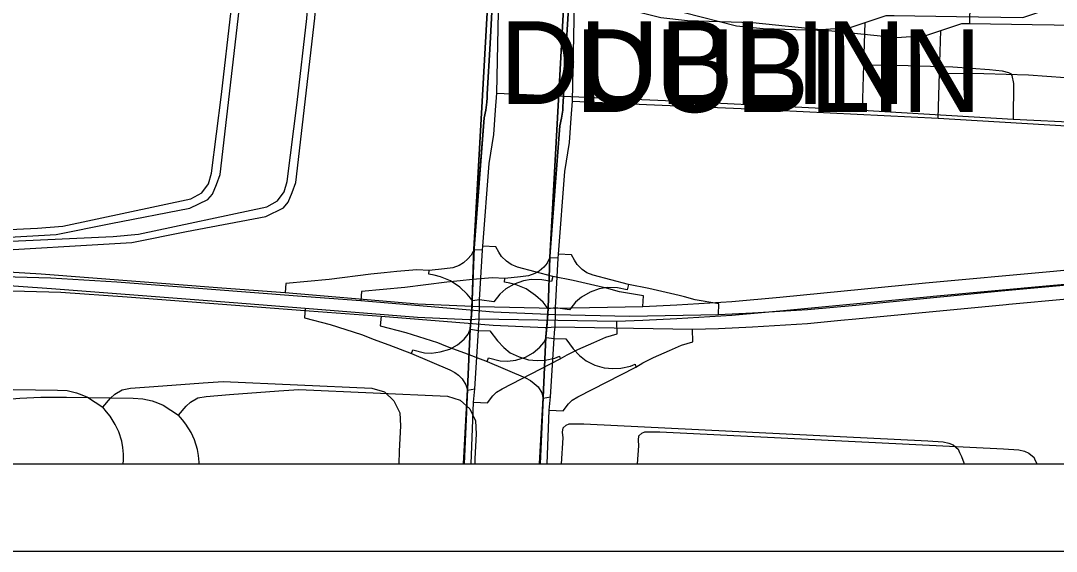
# Model space of a CAD drawing. Extents: x -38.2 to 41.9, y -4 to 24.9.
# Drawn here: x 5.806 to 6.989, y 14 to 14.606 of the extents above; entities that cross this region are included whole.
import ezdxf

# ---------------------------------------------------------------- set-up
doc = ezdxf.new("R2010")
doc.units = 0
for name, color, linetype in [('Default', 7, 'Continuous'), ('GM_X_City_Street', 7, 'Continuous'), ('GM_X_Corporation_Text', 7, 'Continuous'), ('GM_X_County_Road', 7, 'Continuous'), ('GM_X_Interchange_Ramps', 7, 'Continuous'), ('GM_X_Interstate_Location', 7, 'Continuous'), ('GM_X_Interstate_Route', 7, 'Continuous'), ('GM_X_Interstate_Shield', 7, 'Continuous'), ('MT_X_Cells', 7, 'Continuous'), ('SC_Scratch1', 7, 'Continuous'), ('SH_Cut_Line', 7, 'Continuous'), ('SH_Data', 7, 'Continuous')]:
    doc.layers.add(name, color=color, linetype=linetype)

msp = doc.modelspace()

# ---------------------------------------------------------------- linework, layer by layer
at = {"layer": 'Default'}
msp.add_lwpolyline([(2.1, 14.1), (6.3118, 14.1), (6.3164, 14.1849), (6.3196, 14.2542), (6.3213, 14.2711), (6.322, 14.2869), (6.3239, 14.3451), (6.3356, 14.4954), (6.3376, 14.5042), (6.3388, 14.5132), (6.3391, 14.5181), (6.3392, 14.5223), (6.3425, 14.5802), (6.3449, 14.6238), (6.3433, 14.6465), (6.3458, 14.7059), (6.3476, 14.7572), (6.3486, 14.779), (6.3534, 14.8901), (6.365, 15.1468), (6.3733, 15.33), (6.3957, 15.7611)], dxfattribs=at)
at = {"layer": 'GM_X_City_Street'}
msp.add_line((6.3206, 14.1), (6.3235, 14.1704), dxfattribs=at)
for points in [[(6.35, 14.5236), (6.3523, 14.6354), (6.3635, 14.8901)], [(5.2964, 14.3406), (5.4946, 14.3569), (5.6505, 14.3609), (5.8256, 14.3691), (5.8543, 14.3717), (6.0007, 14.4027), (6.0132, 14.4096), (6.0207, 14.42), (6.0241, 14.432), (6.0357, 14.5222), (6.0468, 14.618), (6.0558, 14.7287)], [(5.2978, 14.3315), (5.5096, 14.3476), (5.6655, 14.3516), (5.8468, 14.3621), (5.909, 14.3746), (5.9996, 14.392), (6.0199, 14.4019), (6.0253, 14.4081), (6.0299, 14.4192), (6.034, 14.4306), (6.0558, 14.6186), (6.0639, 14.7286)], [(6.3523, 14.6354), (6.418, 14.6322), (6.4498, 14.6297), (6.4776, 14.6249), (6.5372, 14.6099), (6.5678, 14.6067), (6.6425, 14.6042), (6.72, 14.5965), (6.7537, 14.5988), (6.7708, 14.6045), (6.7946, 14.6123), (6.8037, 14.6122), (6.8751, 14.6112), (6.9508, 14.6101), (6.9749, 14.618), (6.9983, 14.6201)], [(6.7677, 14.5042), (6.7693, 14.5558), (6.7708, 14.6045)], [(6.7693, 14.5558), (6.8197, 14.5552), (6.8709, 14.5536), (6.9128, 14.5507), (6.9273, 14.5489), (6.9345, 14.5471), (6.9366, 14.5462), (6.9382, 14.5439), (6.9401, 14.5345), (6.9397, 14.4938)], [(6.3341, 14.3489), (6.3413, 14.4432), (6.3465, 14.4764), (6.3485, 14.5042), (6.35, 14.5236)], [(6.35, 14.5236), (6.4345, 14.5198), (6.5518, 14.5147), (6.7677, 14.5042), (6.9397, 14.4938), (7.0973, 14.4863), (7.2194, 14.4805)], [(6.3296, 14.2594), (6.33, 14.2657), (6.3304, 14.2797), (6.3304, 14.2875), (6.3335, 14.3442), (6.3341, 14.3489)], [(6.3235, 14.1704), (6.325, 14.1857), (6.3292, 14.2525), (6.3296, 14.2594)], [(5.3301, 14.2038), (5.3623, 14.2023), (5.3911, 14.2005), (5.4282, 14.1983), (5.5962, 14.1881), (5.6279, 14.1859), (5.6713, 14.1832), (5.6952, 14.1824), (5.7186, 14.184), (5.7427, 14.1853), (5.772, 14.1852), (5.8481, 14.1841), (5.8593, 14.1836), (5.87, 14.1811), (5.8761, 14.179), (5.8824, 14.1763), (5.9, 14.1647)], [(5.9, 14.1647), (5.9087, 14.175), (5.9138, 14.1797), (5.9222, 14.1844), (5.9316, 14.1863), (5.9584, 14.1884), (6.0145, 14.1926), (6.0373, 14.194), (6.2073, 14.1866), (6.2216, 14.1821), (6.2326, 14.1719), (6.2392, 14.1583), (6.2401, 14.1433), (6.2386, 14.1146), (6.2381, 14.1)], [(5.9233, 14.1), (5.9235, 14.104), (5.9235, 14.111), (5.9229, 14.1185), (5.9218, 14.1257), (5.9183, 14.1367), (5.9143, 14.1449), (5.9083, 14.1546), (5.9044, 14.1593), (5.9, 14.1647)], [(6.4239, 14.1), (6.4257, 14.1296), (6.4252, 14.1363), (6.4259, 14.1412), (6.4292, 14.1442)], [(6.4292, 14.1442), (6.4326, 14.1458), (6.4496, 14.1456), (6.8424, 14.1263), (6.8597, 14.1252), (6.8664, 14.1237), (6.8711, 14.1215), (6.8772, 14.1163)], [(6.8839, 14.1), (6.8838, 14.1009), (6.8813, 14.1081), (6.8788, 14.1125), (6.8772, 14.1163)]]:
    msp.add_lwpolyline(points, dxfattribs=at)
at = {"layer": 'GM_X_County_Road'}
for points in [[(6.3957, 15.7611), (6.3733, 15.33), (6.365, 15.1468), (6.3534, 14.8903), (6.3486, 14.779), (6.3476, 14.7572), (6.3458, 14.7059), (6.3433, 14.6465), (6.3449, 14.6238), (6.3425, 14.5802), (6.3392, 14.5223), (6.3391, 14.5181), (6.3388, 14.5132), (6.3376, 14.5042), (6.3356, 14.4954), (6.3241, 14.3464), (6.322, 14.2871), (6.3213, 14.2711), (6.3196, 14.2542), (6.3164, 14.1849), (6.3118, 14.1), (8.9, 14.1)], [(2.1, 14.1), (6.3987, 14.1), (6.4028, 14.1757), (6.4061, 14.245), (6.4077, 14.2619), (6.4085, 14.2777), (6.4104, 14.3359), (6.4221, 14.4862), (6.4241, 14.495), (6.4253, 14.504), (6.4255, 14.5089), (6.4257, 14.5131), (6.4289, 14.5711), (6.4314, 14.6146), (6.4298, 14.6373), (6.4323, 14.6967), (6.4341, 14.748), (6.4351, 14.7698), (6.4399, 14.8809), (6.4515, 15.1376), (6.4598, 15.3208), (6.4822, 15.7519)], [(6.4822, 15.7519), (6.4598, 15.3208), (6.4515, 15.1376), (6.4399, 14.8811), (6.4351, 14.7698), (6.4341, 14.748), (6.4323, 14.6967), (6.4298, 14.6373), (6.4314, 14.6146), (6.4289, 14.5711), (6.4257, 14.5131), (6.4255, 14.5089), (6.4253, 14.504), (6.4241, 14.495), (6.4221, 14.4862), (6.4105, 14.3372), (6.4085, 14.2779), (6.4077, 14.2619), (6.4061, 14.245), (6.4028, 14.1757), (6.3987, 14.1), (8.9, 14.1)]]:
    msp.add_lwpolyline(points, dxfattribs=at)
at = {"layer": 'GM_X_Interchange_Ramps'}
for points in [[(2.1, 14.1), (6.3126, 14.1), (6.3164, 14.1849), (6.3196, 14.2542), (6.3207, 14.2654), (6.322, 14.2806), (6.322, 14.2869), (6.3239, 14.3451), (6.3402, 14.6363), (6.3534, 14.8912), (6.3648, 15.1855), (6.3744, 15.3416), (6.3746, 15.3485), (6.3792, 15.4548), (6.3824, 15.5439), (6.3986, 15.8377), (6.4038, 15.9323), (6.4072, 16.1101), (6.413, 16.3602), (5.9853, 16.3764), (5.6874, 16.3954)], [(2.1, 14.1), (6.3995, 14.1), (6.4028, 14.1757), (6.4061, 14.245), (6.4072, 14.2562), (6.4084, 14.2714), (6.4085, 14.2777), (6.4104, 14.3359), (6.4267, 14.6271), (6.4399, 14.882), (6.4513, 15.1763), (6.4608, 15.3324), (6.4611, 15.3393), (6.4657, 15.4456), (6.4689, 15.5348), (6.4851, 15.8285), (6.4903, 15.9231), (6.4937, 16.1009), (6.4995, 16.351), (6.0718, 16.3672), (5.7739, 16.3862)], [(7.1336, 16.3198), (6.4263, 16.3595), (6.413, 16.3602), (6.4072, 16.1101), (6.4038, 15.9323), (6.3986, 15.8377), (6.3824, 15.5439), (6.3792, 15.4548), (6.3746, 15.3485), (6.3744, 15.3416), (6.3648, 15.1855), (6.3534, 14.8912), (6.3402, 14.6363), (6.3239, 14.3451), (6.322, 14.2869), (6.322, 14.2806), (6.3207, 14.2654), (6.3196, 14.2542), (6.3164, 14.1849), (6.3126, 14.1), (8.8984, 14.1)], [(7.2201, 16.3106), (6.5128, 16.3503), (6.4995, 16.351), (6.4937, 16.1009), (6.4903, 15.9231), (6.4851, 15.8285), (6.4689, 15.5348), (6.4657, 15.4456), (6.4611, 15.3393), (6.4608, 15.3324), (6.4513, 15.1763), (6.4399, 14.882), (6.4267, 14.6271), (6.4104, 14.3359), (6.4085, 14.2777), (6.4084, 14.2714), (6.4072, 14.2562), (6.4061, 14.245), (6.4028, 14.1757), (6.3995, 14.1), (8.9, 14.1)], [(6.4142, 14.3142), (6.3738, 14.3246), (6.3665, 14.3276), (6.3611, 14.3314), (6.3554, 14.337), (6.3522, 14.3419), (6.349, 14.3481), (6.3341, 14.3489)], [(6.3231, 14.3425), (6.3209, 14.3384), (6.3171, 14.3341), (6.312, 14.3295), (6.3071, 14.3268), (6.2999, 14.3241), (6.2904, 14.3227), (6.2726, 14.3209)], [(6.3335, 14.3442), (6.3241, 14.3446), (6.3231, 14.3425)], [(6.2215, 14.3183), (6.2063, 14.3166), (6.1585, 14.3106), (6.1089, 14.306), (6.1083, 14.2957)], [(6.2726, 14.3209), (6.2585, 14.3218), (6.2357, 14.3198), (6.2215, 14.3183)], [(6.32, 14.2891), (6.3163, 14.2939), (6.3077, 14.3017), (6.2972, 14.309), (6.2856, 14.3138), (6.2785, 14.3156), (6.2724, 14.3166), (6.2726, 14.3209)], [(6.4142, 14.3142), (6.4126, 14.3082), (6.4013, 14.3103), (6.3894, 14.3106), (6.3805, 14.309), (6.37, 14.3052), (6.3603, 14.2998), (6.3535, 14.2939), (6.3467, 14.285), (6.3304, 14.2875)], [(6.4778, 14.2998), (6.4717, 14.3014), (6.4372, 14.3095), (6.4142, 14.3142)], [(6.3304, 14.2875), (6.3223, 14.2863), (6.32, 14.2891)], [(6.5167, 14.2799), (6.5174, 14.2921), (6.4901, 14.2967), (6.4778, 14.2998)], [(6.1313, 14.2778), (6.1304, 14.267), (6.1598, 14.2593), (6.1956, 14.2477), (6.2004, 14.2458)], [(6.319, 14.2518), (6.3198, 14.2537), (6.3292, 14.2525)], [(6.4225, 14.2198), (6.4303, 14.2244), (6.4426, 14.2306), (6.4609, 14.2388), (6.4744, 14.2448), (6.4875, 14.2486), (6.487, 14.2631)], [(6.2004, 14.2458), (6.209, 14.2424), (6.2267, 14.2358), (6.2525, 14.2261)], [(6.2525, 14.2261), (6.2541, 14.2304), (6.2675, 14.2267), (6.2756, 14.2264), (6.2853, 14.2278), (6.2964, 14.231), (6.305, 14.2359), (6.3128, 14.2426), (6.3174, 14.248), (6.319, 14.2518)], [(6.3292, 14.2525), (6.3422, 14.2521), (6.3508, 14.2404), (6.3579, 14.2329), (6.3654, 14.227), (6.3754, 14.2221), (6.3862, 14.2189), (6.3961, 14.2181), (6.4051, 14.2184), (6.4162, 14.2208), (6.4215, 14.2231), (6.4225, 14.2198)], [(6.2525, 14.2261), (6.2962, 14.2074), (6.3019, 14.2044), (6.3063, 14.2011), (6.3106, 14.1972), (6.3148, 14.1902), (6.3159, 14.1867)], [(6.3235, 14.1704), (6.3393, 14.1698), (6.3454, 14.1776), (6.3498, 14.1819), (6.356, 14.1857), (6.4225, 14.2198)], [(6.3159, 14.1867), (6.3166, 14.1843), (6.325, 14.1857)]]:
    msp.add_lwpolyline(points, dxfattribs=at)
at = {"layer": 'GM_X_Interstate_Location'}
msp.add_line((6.4074, 14.1), (6.4099, 14.1613), dxfattribs=at)
for points in [[(6.4364, 14.5144), (6.4387, 14.6262), (6.45, 14.8809)], [(5.3829, 14.3314), (5.5811, 14.3477), (5.737, 14.3517), (5.912, 14.3599), (5.9407, 14.3625), (6.0872, 14.3935), (6.0997, 14.4004), (6.1072, 14.4108), (6.1106, 14.4228), (6.1221, 14.513), (6.1332, 14.6088), (6.1422, 14.7195)], [(5.3843, 14.3223), (5.596, 14.3384), (5.752, 14.3424), (5.9333, 14.3529), (5.9955, 14.3654), (6.0861, 14.3828), (6.1063, 14.3927), (6.1118, 14.3989), (6.1164, 14.41), (6.1205, 14.4214), (6.1423, 14.6094), (6.1504, 14.7194)], [(6.8902, 14.603), (6.8916, 14.6687)], [(6.4387, 14.6262), (6.5044, 14.623), (6.5363, 14.6205), (6.5641, 14.6157), (6.6237, 14.6007), (6.6543, 14.5975), (6.7289, 14.595), (6.8065, 14.5873), (6.8402, 14.5896), (6.8573, 14.5953), (6.881, 14.6031), (6.8902, 14.603), (6.9616, 14.602), (7.0373, 14.6009)], [(6.8542, 14.495), (6.8558, 14.5466), (6.8573, 14.5953)], [(6.8558, 14.5466), (6.9062, 14.546), (6.9574, 14.5444), (6.9993, 14.5415), (7.0138, 14.5397), (7.021, 14.5379), (7.023, 14.537), (7.0247, 14.5348), (7.0266, 14.5253), (7.0262, 14.4847)], [(6.4206, 14.3397), (6.4278, 14.4341), (6.4329, 14.4672), (6.435, 14.495), (6.4364, 14.5144)], [(6.4364, 14.5144), (6.521, 14.5106), (6.6382, 14.5055), (6.8542, 14.495), (7.0262, 14.4847), (7.1838, 14.4771), (7.3059, 14.4713)], [(6.4161, 14.2502), (6.4165, 14.2565), (6.4169, 14.2705), (6.4169, 14.2783), (6.42, 14.335), (6.4206, 14.3397)], [(6.4099, 14.1613), (6.4115, 14.1765), (6.4156, 14.2433), (6.4161, 14.2502)], [(5.4166, 14.1946), (5.4488, 14.1931), (5.4776, 14.1913), (5.5146, 14.1891), (5.6827, 14.1789), (5.7144, 14.1767), (5.7577, 14.174), (5.7817, 14.1732), (5.8051, 14.1749), (5.8292, 14.1761), (5.8585, 14.176), (5.9346, 14.1749), (5.9458, 14.1744), (5.9565, 14.1719), (5.9626, 14.1698), (5.9689, 14.1671), (5.9865, 14.1555)], [(5.9865, 14.1555), (5.9952, 14.1659), (6.0002, 14.1705), (6.0087, 14.1752), (6.0181, 14.1771), (6.0448, 14.1792), (6.1009, 14.1834), (6.1238, 14.1848), (6.2938, 14.1774), (6.3081, 14.1729), (6.3191, 14.1627), (6.3256, 14.1492), (6.3265, 14.1342), (6.3251, 14.1055), (6.3249, 14.1)], [(6.0099, 14.1), (6.0099, 14.1018), (6.0094, 14.1093), (6.0083, 14.1165), (6.0048, 14.1275), (6.0008, 14.1357), (5.9947, 14.1454), (5.9909, 14.1501), (5.9865, 14.1555)], [(6.5109, 14.1), (6.5122, 14.1204), (6.5117, 14.1271), (6.5124, 14.132), (6.5157, 14.135)], [(6.5157, 14.135), (6.5191, 14.1366), (6.5361, 14.1364), (6.9289, 14.1171), (6.9462, 14.116), (6.9529, 14.1145), (6.9576, 14.1123), (6.9637, 14.1071)], [(6.9672, 14.1), (6.9653, 14.1033), (6.9637, 14.1071)]]:
    msp.add_lwpolyline(points, dxfattribs=at)
at = {"layer": 'GM_X_Interstate_Route'}
for points in [[(6.5167, 14.2799), (6.5556, 14.2817), (6.6184, 14.2856), (6.6734, 14.2906), (6.8396, 14.3067), (6.9816, 14.3198), (7.151, 14.3359), (7.3033, 14.3494), (7.5456, 14.3729), (7.6751, 14.3847), (7.9786, 14.413), (8.1142, 14.4259), (8.3008, 14.4428), (8.541, 14.4652), (8.7035, 14.4808), (8.7658, 14.4853), (8.8195, 14.4882), (8.8708, 14.4895), (8.9, 14.4903)], [(5.7541, 14.3218), (5.8295, 14.3172), (6.0359, 14.3012), (6.1083, 14.2957), (6.2597, 14.283), (6.3222, 14.2801), (6.3304, 14.2797), (6.4155, 14.2779), (6.5167, 14.2799)], [(6.3189, 14.265), (6.3209, 14.2649), (6.33, 14.2657), (6.487, 14.2631), (6.5167, 14.264), (6.5556, 14.2659), (6.6184, 14.2697), (6.6564, 14.2732), (6.6734, 14.2747), (6.8455, 14.2912), (6.8485, 14.2914), (6.9816, 14.3039), (7.1491, 14.3186)], [(5.1897, 14.2651), (5.1986, 14.2666), (5.2607, 14.2765), (5.3478, 14.289), (5.4392, 14.2993), (5.5116, 14.3041), (5.6143, 14.3079), (5.6961, 14.3072), (5.7656, 14.3055), (5.8413, 14.3002), (6.0492, 14.2842), (6.1313, 14.2778), (6.2595, 14.2677), (6.3189, 14.265)]]:
    msp.add_lwpolyline(points, dxfattribs=at)
at = {"layer": 'MT_X_Cells'}
for points in [[(6.42, 14.335), (6.4106, 14.3354), (6.4095, 14.3333)], [(6.5006, 14.305), (6.4602, 14.3154), (6.453, 14.3184), (6.4476, 14.3222), (6.4419, 14.3279), (6.4387, 14.3327), (6.4354, 14.3389), (6.4206, 14.3397)], [(6.4095, 14.3333), (6.4074, 14.3292), (6.4036, 14.3249), (6.3985, 14.3203), (6.3936, 14.3176), (6.3863, 14.3149), (6.3769, 14.3136), (6.3591, 14.3117)], [(6.3591, 14.3117), (6.345, 14.3126), (6.3222, 14.3107), (6.308, 14.3091)], [(6.308, 14.3091), (6.2928, 14.3074), (6.245, 14.3014), (6.1954, 14.2968), (6.1948, 14.2865)], [(6.4065, 14.28), (6.4028, 14.2847), (6.3942, 14.2925), (6.3836, 14.2998), (6.3721, 14.3047), (6.365, 14.3064), (6.3588, 14.3075), (6.3591, 14.3117)], [(6.5006, 14.305), (6.4991, 14.299), (6.4878, 14.3011), (6.4759, 14.3014), (6.467, 14.2998), (6.4565, 14.296), (6.4468, 14.2906), (6.44, 14.2847), (6.4332, 14.2758), (6.4169, 14.2783)], [(6.5643, 14.2907), (6.5582, 14.2922), (6.5236, 14.3003), (6.5006, 14.305)], [(6.6032, 14.2707), (6.6038, 14.2829), (6.5766, 14.2875), (6.5643, 14.2907)], [(6.4169, 14.2783), (6.4087, 14.2771), (6.4065, 14.28)], [(6.2178, 14.2686), (6.2169, 14.2578), (6.2463, 14.2501), (6.2821, 14.2385), (6.2869, 14.2366)], [(6.509, 14.2106), (6.5168, 14.2152), (6.5291, 14.2214), (6.5474, 14.2296), (6.5609, 14.2356), (6.574, 14.2394), (6.5735, 14.2539)], [(6.339, 14.2169), (6.3406, 14.2212), (6.354, 14.2175), (6.3621, 14.2172), (6.3718, 14.2186), (6.3828, 14.2218), (6.3915, 14.2267), (6.3993, 14.2334), (6.4039, 14.2388), (6.4055, 14.2426)], [(6.4055, 14.2426), (6.4063, 14.2445), (6.4156, 14.2433)], [(6.4156, 14.2433), (6.4287, 14.2429), (6.4373, 14.2313), (6.4443, 14.2237), (6.4519, 14.2178), (6.4619, 14.2129), (6.4727, 14.2097), (6.4825, 14.2089), (6.4915, 14.2092), (6.5027, 14.2116), (6.508, 14.2139), (6.509, 14.2106)], [(6.2869, 14.2366), (6.2954, 14.2332), (6.3132, 14.2267), (6.339, 14.2169)], [(6.339, 14.2169), (6.3827, 14.1982), (6.3884, 14.1952), (6.3928, 14.1919), (6.3971, 14.1881), (6.4013, 14.1811), (6.4024, 14.1775)], [(6.4099, 14.1613), (6.4258, 14.1606), (6.4319, 14.1684), (6.4362, 14.1727), (6.4424, 14.1765), (6.509, 14.2106)], [(6.4024, 14.1775), (6.4031, 14.1751), (6.4115, 14.1765)]]:
    msp.add_lwpolyline(points, dxfattribs=at)
at = {"layer": 'SC_Scratch1'}
for points in [[(6.6032, 14.2707), (6.642, 14.2726), (6.7048, 14.2764), (6.7599, 14.2814), (6.926, 14.2975), (7.068, 14.3106), (7.2374, 14.3267), (7.3898, 14.3402), (7.6321, 14.3637), (7.7616, 14.3755), (8.0651, 14.4038), (8.2007, 14.4167), (8.3873, 14.4336), (8.6275, 14.456), (8.79, 14.4716), (8.8523, 14.4761), (8.9, 14.4787)], [(6.4054, 14.2558), (6.4074, 14.2557), (6.4165, 14.2565), (6.5735, 14.2539), (6.6032, 14.2548), (6.642, 14.2567), (6.7048, 14.2605), (6.7429, 14.264), (6.7599, 14.2656), (6.9319, 14.282), (6.9349, 14.2823), (7.068, 14.2947), (7.2356, 14.3094), (7.3898, 14.3243), (7.6267, 14.3465), (7.7648, 14.3601), (8.0651, 14.3879), (8.2007, 14.4009), (8.3873, 14.4178), (8.6275, 14.4401), (8.7229, 14.4493), (8.79, 14.4557), (8.8512, 14.461), (8.9, 14.464)], [(5.7726, 14.3146), (5.8405, 14.3126), (5.916, 14.308), (6.1224, 14.292), (6.1948, 14.2865), (6.3462, 14.2738), (6.4087, 14.2709), (6.4169, 14.2705), (6.502, 14.2687), (6.6032, 14.2707)], [(5.2761, 14.256), (5.2851, 14.2574), (5.3472, 14.2673), (5.4343, 14.2798), (5.5257, 14.2901), (5.5981, 14.2949), (5.7007, 14.2987), (5.7826, 14.298), (5.8521, 14.2963), (5.9277, 14.291), (6.1357, 14.275), (6.2178, 14.2686), (6.346, 14.2585), (6.4054, 14.2558)]]:
    msp.add_lwpolyline(points, dxfattribs=at)
at = {"layer": 'SH_Cut_Line'}
msp.add_lwpolyline([(2.1, 14.1), (8.9, 14.1), (8.9, 16.2272), (7.9696, 16.2752), (7.6901, 16.2894), (7.5793, 16.2961), (7.3442, 16.3107), (7.1336, 16.3198), (6.4263, 16.3595), (6.413, 16.3602), (5.9853, 16.3764), (5.6874, 16.3954)], dxfattribs=at)
at = {"layer": 'SH_Data'}
for p, q in [((2.1, 14.1), (8.9, 14.1)), ((2, 14), (9, 14))]:
    msp.add_line(p, q, dxfattribs=at)

# ---------------------------------------------------------------- texts
at = {"layer": 'GM_X_Corporation_Text'}
msp.add_text('DUBLIN', height=0.0947, rotation=0, dxfattribs=at).set_placement((6.353, 14.5111))
at = {"layer": 'GM_X_Interstate_Shield'}
msp.add_text('DUBLIN', height=0.0947, rotation=0, dxfattribs=at).set_placement((6.4394, 14.5019))

doc.saveas('drawing.dxf')
